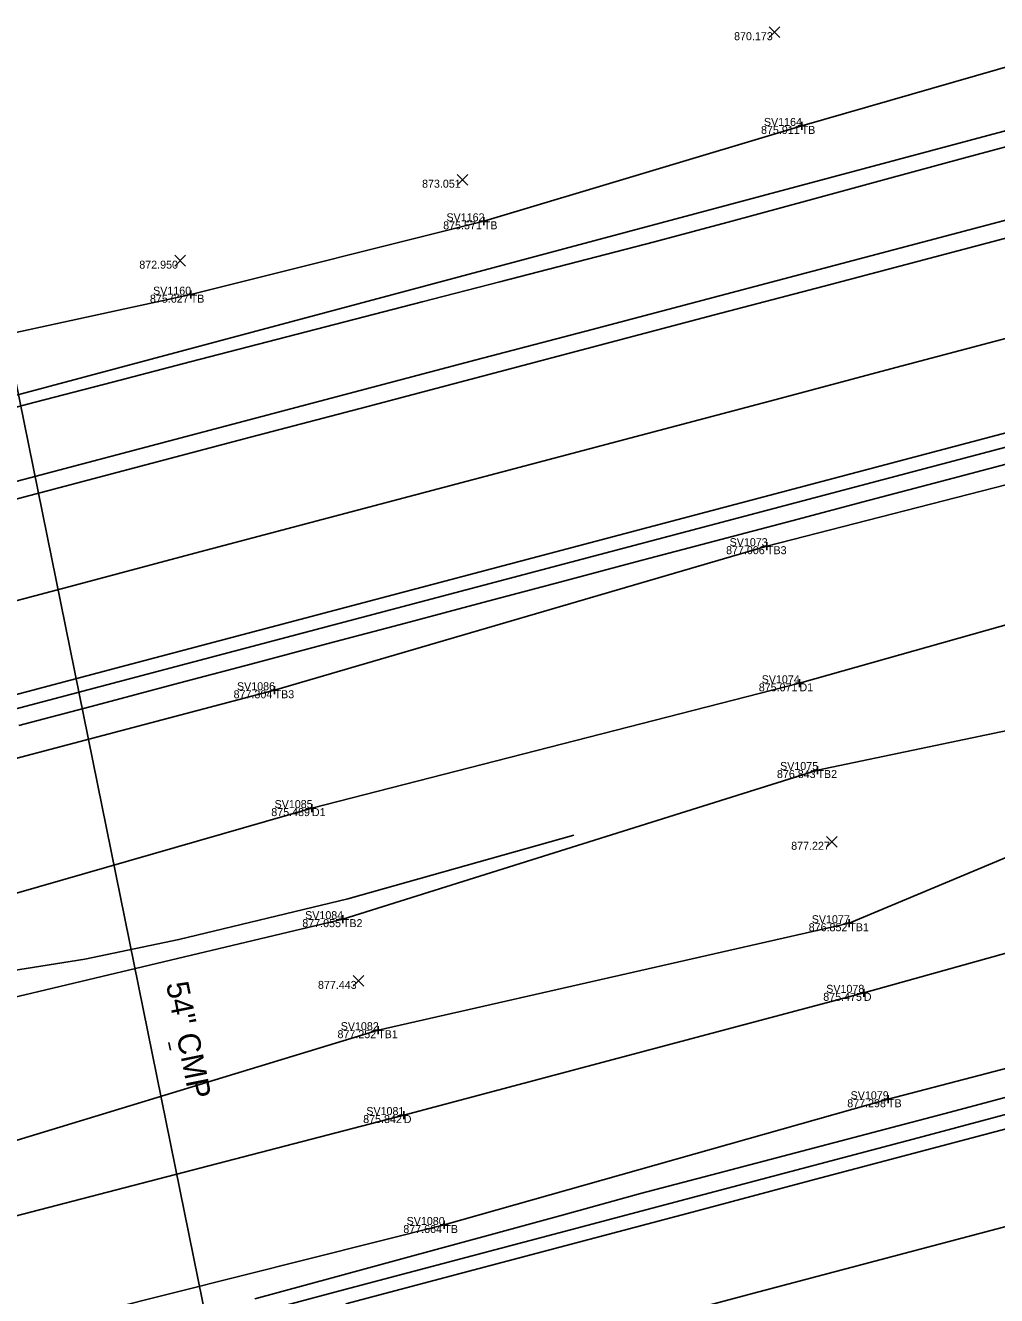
# Model space of a CAD drawing. Extents: x 2125299 to 2129212, y 713100 to 714300.
# Drawn here: x 2128294.5 to 2128416, y 713987.2 to 714146 of the extents above; entities that cross this region are included whole.
import ezdxf

# ---------------------------------------------------------------- set-up
doc = ezdxf.new("R2010")
doc.units = 0
for name, color, linetype in [('_CIVIL_CONSTRUCTION', 7, 'Continuous'), ('DR_X_Ditch', 7, 'Continuous'), ('DR_X_Storm_Sewer', 7, 'Continuous'), ('DR_X_Text', 7, 'Continuous'), ('PV_X_EOP', 7, 'Continuous'), ('PV_X_Shoulder_Rumble_Strip', 7, 'Continuous'), ('RS_Raster1', 7, 'Continuous'), ('RW_P_Esmt_TMP', 7, 'Continuous'), ('RW_X_Esmt_CH', 7, 'Continuous'), ('RW_X_Fee_WL', 7, 'Continuous'), ('SC_Scratch1', 7, 'Continuous'), ('SC_Scratch2', 7, 'Continuous'), ('SV_X_Mon_Cells_Found', 7, 'Continuous'), ('SV_X_Text_Elevation', 7, 'Continuous'), ('SV_X_Top_of_Bank', 7, 'Continuous')]:
    doc.layers.add(name, color=color, linetype=linetype)

msp = doc.modelspace()

# ---------------------------------------------------------------- linework, layer by layer
at = {"layer": '_CIVIL_CONSTRUCTION'}
for points in [[(2128156.2, 714037.91), (2128170.7, 714041.73), (2128185.21, 714045.56), (2128199.71, 714049.38), (2128214.22, 714053.21), (2128228.72, 714057.03), (2128243.22, 714060.86), (2128257.73, 714064.68), (2128272.23, 714068.51), (2128286.73, 714072.34), (2128301.23, 714076.18), (2128315.73, 714080.03), (2128330.23, 714083.87), (2128344.73, 714087.71), (2128359.23, 714091.55), (2128373.73, 714095.39), (2128388.23, 714099.23), (2128402.73, 714103.07), (2128417.23, 714106.91)], [(2128370.32, 713983.48), (2128384.82, 713987.32), (2128399.32, 713991.16), (2128413.82, 713995), (2128428.32, 713998.85)]]:
    msp.add_lwpolyline(points, dxfattribs=at)
at = {"layer": 'DR_X_Ditch'}
for points in [[(2128525.29, 714099.16), (2128497.16, 714092.88), (2128436.33, 714076.51), (2128391.32, 714063.78), (2128330.37, 714048.18), (2128276.31, 714032.64)], [(2128539.96, 714065.48), (2128533.93, 714063.76), (2128504.91, 714054.76), (2128447.02, 714038.39), (2128399.37, 714025.09), (2128341.85, 714009.81), (2128283.6, 713994.68), (2128242.74, 713988.86), (2128205.78, 713990.56), (2128171.48, 713986), (2128143.07, 713980.05), (2128117.8, 713975.62)]]:
    msp.add_lwpolyline(points, dxfattribs=at)
at = {"layer": 'DR_X_Storm_Sewer'}
msp.add_line((2128282.88, 714152.99), (2128337.68, 713883.12), dxfattribs=at)
at = {"layer": 'DR_X_Text'}
msp.add_line((2128312.67, 714017.94), (2128312.48, 714018.89), dxfattribs=at)
at = {"layer": 'PV_X_EOP'}
for points in [[(2128286.1, 714096.37), (2128295.77, 714098.93), (2128305.45, 714101.44), (2128315.13, 714103.95), (2128324.8, 714106.47), (2128334.49, 714108.97), (2128344.17, 714111.46), (2128353.85, 714113.96), (2128363.54, 714116.45), (2128373.22, 714118.95), (2128382.87, 714121.56), (2128392.53, 714124.18), (2128402.18, 714126.79), (2128411.83, 714129.41), (2128421.48, 714132.02)], [(2128293.72, 714058.5), (2128303.39, 714061.06), (2128313.06, 714063.62), (2128322.72, 714066.19), (2128332.39, 714068.75), (2128342.05, 714071.31), (2128351.72, 714073.88), (2128361.38, 714076.44), (2128371.05, 714079), (2128380.72, 714081.55), (2128390.39, 714084.11), (2128400.06, 714086.66), (2128409.73, 714089.22), (2128419.39, 714091.77)], [(2128323.24, 713986.82), (2128332.89, 713989.45), (2128342.53, 713992.09), (2128352.18, 713994.72), (2128361.82, 713997.36), (2128371.47, 714000), (2128381.14, 714002.56), (2128390.81, 714005.1), (2128400.48, 714007.65), (2128410.15, 714010.19), (2128419.82, 714012.74)]]:
    msp.add_lwpolyline(points, dxfattribs=at)
at = {"layer": 'PV_X_Shoulder_Rumble_Strip'}
for points in [[(2128099.62, 714037.93), (2128104.35, 714039.18), (2128118.85, 714043), (2128133.35, 714046.83), (2128147.86, 714050.65), (2128162.36, 714054.48), (2128176.86, 714058.3), (2128191.37, 714062.13), (2128205.87, 714065.95), (2128220.37, 714069.78), (2128234.88, 714073.6), (2128249.38, 714077.43), (2128263.89, 714081.25), (2128278.39, 714085.07), (2128292.89, 714088.9), (2128307.4, 714092.72), (2128321.9, 714096.55), (2128336.4, 714100.37), (2128350.91, 714104.2), (2128365.41, 714108.02), (2128379.92, 714111.85), (2128394.42, 714115.67), (2128408.92, 714119.5), (2128423.43, 714123.32)], [(2128092.76, 714007.7), (2128103.1, 714010.43), (2128117.61, 714014.25), (2128132.11, 714018.07), (2128146.62, 714021.89), (2128161.12, 714025.71), (2128175.62, 714029.53), (2128190.13, 714033.35), (2128204.63, 714037.17), (2128219.14, 714040.99), (2128233.64, 714044.81), (2128248.15, 714048.63), (2128262.65, 714052.45), (2128277.16, 714056.28), (2128291.66, 714060.12), (2128306.16, 714063.95), (2128320.66, 714067.79), (2128335.16, 714071.62), (2128349.66, 714075.46), (2128364.16, 714079.29), (2128378.66, 714083.13), (2128393.16, 714086.96), (2128407.66, 714090.8), (2128422.17, 714094.63)], [(2128319.18, 713983.94), (2128333.68, 713987.78), (2128348.18, 713991.62), (2128362.68, 713995.46), (2128377.18, 713999.3), (2128391.68, 714003.14), (2128406.18, 714006.98), (2128420.68, 714010.82)]]:
    msp.add_lwpolyline(points, dxfattribs=at)
at = {"layer": 'RS_Raster1'}
msp.add_lwpolyline([(2128363.11, 714044.81), (2128334.85, 714036.86), (2128313.75, 714031.74), (2128301.97, 714029.31), (2128286.46, 714026.84), (2128257.87, 714023.95), (2128247.5, 714023.4), (2128226.75, 714021.68), (2128205.39, 714019.64), (2128190.35, 714018), (2128171.93, 714016.23), (2128154.59, 714013.93), (2128141.53, 714011.83), (2128129.8, 714009.97), (2128117.74, 714007.84), (2128109.17, 714006.09), (2128099.58, 714004.27), (2128089.89, 714001.93)], dxfattribs=at)
at = {"layer": 'SC_Scratch1'}
msp.add_lwpolyline([(2128628.95, 714194.22), (2128585.4, 714182.79), (2128564.12, 714177.04), (2128556.66, 714174.91), (2128549.07, 714172.15), (2128542.5, 714169.81), (2128530.23, 714165.43), (2128519.08, 714161.63), (2128507.97, 714157.87), (2128491.85, 714153.02), (2128450.41, 714141.74), (2128284.96, 714097.53), (2128098.63, 714048.44)], dxfattribs=at)
at = {"layer": 'SC_Scratch2'}
for points in [[(2128163.14, 714052.45), (2128177.64, 714056.28), (2128192.15, 714060.1), (2128206.65, 714063.93), (2128221.16, 714067.75), (2128235.66, 714071.58), (2128250.17, 714075.4), (2128264.67, 714079.23), (2128279.17, 714083.05), (2128293.68, 714086.88), (2128308.18, 714090.7), (2128322.69, 714094.53), (2128337.19, 714098.35), (2128351.69, 714102.18), (2128366.2, 714106), (2128380.7, 714109.83), (2128395.21, 714113.65), (2128409.71, 714117.48), (2128424.21, 714121.3)], [(2128160.65, 714027.38), (2128175.15, 714031.2), (2128189.66, 714035.02), (2128204.16, 714038.84), (2128218.67, 714042.66), (2128233.17, 714046.48), (2128247.68, 714050.3), (2128262.18, 714054.12), (2128276.69, 714057.95), (2128291.19, 714061.78), (2128305.69, 714065.62), (2128320.19, 714069.46), (2128334.69, 714073.29), (2128349.19, 714077.13), (2128363.69, 714080.96), (2128378.2, 714084.8), (2128392.7, 714088.63), (2128407.2, 714092.47), (2128421.7, 714096.3)], [(2128334.59, 713986.21), (2128349.09, 713990.05), (2128363.59, 713993.89), (2128378.09, 713997.73), (2128392.59, 714001.57), (2128407.09, 714005.42), (2128421.59, 714009.26)]]:
    msp.add_lwpolyline(points, dxfattribs=at)
at = {"layer": 'SV_X_Mon_Cells_Found'}
for p, q in [((2128391.1, 714133.45), (2128392.1, 714133.45)), ((2128391.6, 714133.95), (2128391.6, 714132.95)), ((2128391.6, 714133.45), (2128391.6, 714133.45)), ((2128351.36, 714121.53), (2128352.36, 714121.53)), ((2128351.86, 714122.03), (2128351.86, 714121.03)), ((2128351.86, 714121.53), (2128351.86, 714121.53)), ((2128314.72, 714112.36), (2128315.72, 714112.36)), ((2128315.22, 714112.86), (2128315.22, 714111.86)), ((2128315.22, 714112.36), (2128315.22, 714112.36)), ((2128386.76, 714080.92), (2128387.76, 714080.92)), ((2128387.26, 714081.42), (2128387.26, 714080.42)), ((2128387.26, 714080.92), (2128387.26, 714080.92)), ((2128325.2, 714062.91), (2128326.2, 714062.91)), ((2128325.7, 714063.41), (2128325.7, 714062.41)), ((2128325.7, 714062.91), (2128325.7, 714062.91)), ((2128390.82, 714063.78), (2128391.82, 714063.78)), ((2128391.32, 714064.28), (2128391.32, 714063.28)), ((2128391.32, 714063.78), (2128391.32, 714063.78)), ((2128393.57, 714053.44), (2128393.57, 714052.44)), ((2128393.07, 714052.94), (2128394.07, 714052.94)), ((2128393.57, 714052.94), (2128393.57, 714052.94)), ((2128330.37, 714048.68), (2128330.37, 714047.68)), ((2128329.87, 714048.18), (2128330.87, 714048.18)), ((2128330.37, 714048.18), (2128330.37, 714048.18)), ((2128333.74, 714034.3), (2128334.74, 714034.3)), ((2128334.24, 714034.8), (2128334.24, 714033.8)), ((2128334.24, 714034.3), (2128334.24, 714034.3)), ((2128397.55, 714034.29), (2128397.55, 714033.29)), ((2128397.05, 714033.79), (2128398.05, 714033.79)), ((2128397.55, 714033.79), (2128397.55, 714033.79)), ((2128398.87, 714025.09), (2128399.87, 714025.09)), ((2128399.37, 714025.59), (2128399.37, 714024.59)), ((2128399.37, 714025.09), (2128399.37, 714025.09)), ((2128338.15, 714020.42), (2128339.15, 714020.42)), ((2128338.65, 714020.92), (2128338.65, 714019.92)), ((2128338.65, 714020.42), (2128338.65, 714020.42)), ((2128402.4, 714012.29), (2128402.4, 714011.29)), ((2128401.9, 714011.79), (2128402.9, 714011.79)), ((2128402.4, 714011.79), (2128402.4, 714011.79)), ((2128341.35, 714009.81), (2128342.35, 714009.81)), ((2128341.85, 714010.31), (2128341.85, 714009.31)), ((2128341.85, 714009.81), (2128341.85, 714009.81)), ((2128346.42, 713996.07), (2128347.42, 713996.07)), ((2128346.92, 713996.57), (2128346.92, 713995.57)), ((2128346.92, 713996.07), (2128346.92, 713996.07))]:
    msp.add_line(p, q, dxfattribs=at)
at = {"layer": 'SV_X_Text_Elevation'}
for p, q in [((2128387.55, 714144.51), (2128388.88, 714145.84)), ((2128387.55, 714145.84), (2128388.88, 714144.51)), ((2128348.55, 714126.06), (2128349.88, 714127.4)), ((2128348.55, 714127.4), (2128349.88, 714126.06)), ((2128313.23, 714115.94), (2128314.57, 714117.28)), ((2128313.23, 714117.28), (2128314.57, 714115.94)), ((2128394.72, 714043.3), (2128396.05, 714044.63)), ((2128394.72, 714044.63), (2128396.05, 714043.3)), ((2128335.53, 714025.92), (2128336.86, 714027.25)), ((2128335.53, 714027.25), (2128336.86, 714025.92))]:
    msp.add_line(p, q, dxfattribs=at)
at = {"layer": 'SV_X_Top_of_Bank'}
for points in [[(2128105.46, 714054.71), (2128114.11, 714060.74), (2128124.65, 714063.56), (2128152.61, 714070.67), (2128179.16, 714077.14), (2128212.09, 714085.22), (2128215.23, 714083.5), (2128232.87, 714085.47), (2128251.15, 714091.35), (2128260.26, 714099.99), (2128265.91, 714101.36), (2128273.54, 714100.32), (2128289.09, 714106.73), (2128315.22, 714112.36), (2128351.86, 714121.53), (2128391.6, 714133.45), (2128421.6, 714142.07), (2128443.7, 714149.09)], [(2128621.75, 714139.89), (2128575.4, 714127.43), (2128536.54, 714118.82), (2128494.56, 714106.73), (2128494.59, 714106.74), (2128431.42, 714092.25), (2128387.26, 714080.92), (2128325.7, 714062.91), (2128270.25, 714048.29), (2128232.44, 714039), (2128192.57, 714028.85), (2128120.54, 714010.42)], [(2128630.23, 714112.45), (2128582.67, 714099.87), (2128543.67, 714088.86), (2128499.9, 714077.56), (2128440.42, 714062.73), (2128393.57, 714052.94), (2128334.24, 714034.3), (2128278.14, 714020.98), (2128236.99, 714017.4), (2128194.11, 714013.25), (2128178.62, 714010.69), (2128139.13, 714003.23), (2128093.27, 713996.96)], [(2128632.64, 714103.31), (2128584.74, 714089.99), (2128545.97, 714080.06), (2128501.31, 714068.27), (2128443.11, 714052.88), (2128397.55, 714033.79), (2128338.65, 714020.42), (2128280.89, 714002.86), (2128241.69, 713997.86), (2128197.7, 714003.21), (2128178.62, 714010.69)], [(2128641.06, 714074.44), (2128591.12, 714062.19), (2128554.7, 714051.88), (2128508.37, 714039.66), (2128452.53, 714024.9), (2128402.4, 714011.79), (2128346.92, 713996.07), (2128287.48, 713981.18), (2128247.17, 713969.96), (2128213.74, 713962.2), (2128176.95, 713953.14), (2128149.75, 713946.28), (2128088.07, 713932.71), (2128089.34, 713952.15), (2128089.79, 713973.52), (2128093.27, 713996.96)]]:
    msp.add_lwpolyline(points, dxfattribs=at)

# ---------------------------------------------------------------- texts
at = {"layer": 'DR_X_Text'}
msp.add_text('54" CMP', height=2.8, rotation=281.4792, dxfattribs=at).set_placement((2128312.12, 714026.2))
at = {"layer": 'RW_P_Esmt_TMP'}
for s, p in [('TB', (2128391.6, 714132.45)), ('TB', (2128351.86, 714120.53)), ('TB', (2128315.22, 714111.36)), ('TB3', (2128387.26, 714079.92)), ('TB3', (2128325.7, 714061.91)), ('D1', (2128391.32, 714062.78)), ('TB2', (2128393.57, 714051.94)), ('D1', (2128330.37, 714047.18)), ('TB2', (2128334.24, 714033.3)), ('TB1', (2128397.55, 714032.79)), ('D', (2128399.37, 714024.09)), ('TB1', (2128338.65, 714019.42)), ('TB', (2128402.4, 714010.79)), ('D', (2128341.85, 714008.81)), ('TB', (2128346.92, 713995.07))]:
    msp.add_text(s, height=1, dxfattribs=at).set_placement(p)
at = {"layer": 'RW_X_Esmt_CH'}
for s, p in [('SV1164', (2128386.88, 714133.45)), ('SV1162', (2128347.19, 714121.53)), ('SV1160', (2128310.51, 714112.36)), ('SV1073', (2128382.59, 714080.92)), ('SV1074', (2128386.6, 714063.78)), ('SV1086', (2128321, 714062.91)), ('SV1075', (2128388.9, 714052.94)), ('SV1085', (2128325.7, 714048.18)), ('SV1084', (2128329.52, 714034.3)), ('SV1077', (2128392.86, 714033.79)), ('SV1078', (2128394.67, 714025.09)), ('SV1082', (2128333.97, 714020.42)), ('SV1079', (2128397.72, 714011.79)), ('SV1081', (2128337.17, 714009.81)), ('SV1080', (2128342.21, 713996.07))]:
    msp.add_text(s, height=1, dxfattribs=at).set_placement(p)
at = {"layer": 'RW_X_Fee_WL'}
for s, p in [('870.173', (2128383.15, 714144.17)), ('875.911', (2128386.52, 714132.45)), ('873.051', (2128344.14, 714125.73)), ('875.571', (2128346.78, 714120.53)), ('872.950', (2128308.79, 714115.61)), ('875.627', (2128310.12, 714111.36)), ('877.006', (2128382.15, 714079.92)), ('877.304', (2128320.58, 714061.91)), ('875.071', (2128386.24, 714062.78)), ('876.843', (2128388.51, 714051.94)), ('875.489', (2128325.29, 714047.18)), ('877.227', (2128390.29, 714042.97)), ('877.055', (2128329.17, 714033.3)), ('876.852', (2128392.48, 714032.79)), ('877.443', (2128331.13, 714025.58)), ('875.475', (2128394.3, 714024.09)), ('877.252', (2128333.57, 714019.42)), ('877.298', (2128397.3, 714010.79)), ('875.842', (2128336.78, 714008.81)), ('877.664', (2128341.8, 713995.07))]:
    msp.add_text(s, height=1, dxfattribs=at).set_placement(p)

doc.saveas('drawing.dxf')
